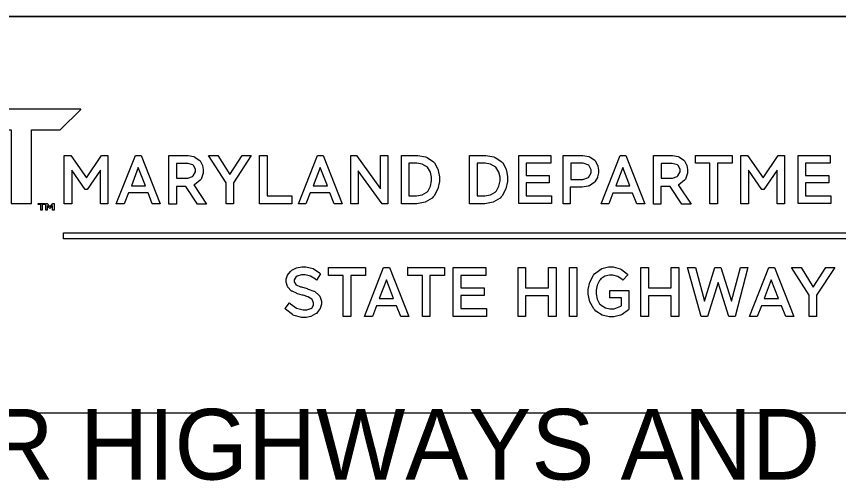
# Model space of a CAD drawing. Extents: x -113.6 to -105.1, y -201.8 to -190.8.
# Drawn here: x -108.497 to -107.419, y -200.619 to -200.01 of the extents above; entities that cross this region are included whole.
import ezdxf

# ---------------------------------------------------------------- set-up
doc = ezdxf.new("R2010")
doc.units = 0
for name, color, linetype in [('BORD-LINE', 7, 'Continuous'), ('MSHA-LOGO', 7, 'Continuous'), ('TTLB-TEXT', 7, 'Continuous'), ('USER-LINE', 7, 'Continuous')]:
    doc.layers.add(name, color=color, linetype=linetype)

msp = doc.modelspace()

# ---------------------------------------------------------------- linework, layer by layer
at = {"layer": 'BORD-LINE'}
msp.add_line((-105.4316, -200.01), (-109.9045, -200.01), dxfattribs=at)
at = {"layer": 'MSHA-LOGO'}
for points in [[(-108.5686, -200.1319), (-108.5686, -200.1591), (-108.5042, -200.1591), (-108.5042, -200.2556), (-108.4773, -200.2556), (-108.4773, -200.1591), (-108.4397, -200.1591), (-108.4127, -200.1321), (-108.4127, -200.1319)], [(-108.4345, -200.1924), (-108.4256, -200.1924), (-108.4053, -200.222), (-108.3857, -200.1924), (-108.3772, -200.1924), (-108.3772, -200.2559), (-108.387, -200.2559), (-108.387, -200.2118), (-108.4043, -200.2371), (-108.407, -200.2371), (-108.4246, -200.2118), (-108.4246, -200.2559), (-108.4345, -200.2559)], [(-108.3409, -200.1924), (-108.3333, -200.1924), (-108.3085, -200.2559), (-108.3189, -200.2559), (-108.3245, -200.2418), (-108.3503, -200.2418), (-108.3559, -200.2559), (-108.3661, -200.2559)], [(-108.297, -200.2562), (-108.297, -200.1927), (-108.2748, -200.1927), (-108.272, -200.1927), (-108.2644, -200.1941), (-108.2636, -200.1944), (-108.2629, -200.1946), (-108.2572, -200.1985), (-108.2568, -200.199), (-108.2563, -200.1995), (-108.2534, -200.2047), (-108.2532, -200.2053), (-108.253, -200.2058), (-108.2522, -200.2111), (-108.2522, -200.2128), (-108.2522, -200.2157), (-108.2549, -200.2235), (-108.2554, -200.2243), (-108.256, -200.2251), (-108.2636, -200.2309), (-108.2646, -200.2312), (-108.2476, -200.2566), (-108.2597, -200.2566), (-108.2751, -200.2332), (-108.2872, -200.2332), (-108.2872, -200.2566), (-108.297, -200.2566)], [(-108.2123, -200.2286), (-108.2123, -200.2562), (-108.2221, -200.2562), (-108.2221, -200.2286), (-108.245, -200.1924), (-108.2329, -200.1924), (-108.2172, -200.2177), (-108.2011, -200.1924), (-108.1893, -200.1924)], [(-108.1782, -200.1924), (-108.1684, -200.1924), (-108.1684, -200.2457), (-108.136, -200.2457), (-108.136, -200.2559), (-108.1782, -200.2559)], [(-108.1023, -200.1924), (-108.0948, -200.1924), (-108.0699, -200.2559), (-108.0804, -200.2559), (-108.0859, -200.2418), (-108.1118, -200.2418), (-108.1173, -200.2559), (-108.1272, -200.2559)], [(-108.0175, -200.2562), (-108.049, -200.2128), (-108.049, -200.2562), (-108.0584, -200.2562), (-108.0584, -200.1927), (-108.0509, -200.1927), (-108.0195, -200.2362), (-108.0195, -200.1927), (-108.01, -200.1927), (-108.01, -200.2562)], [(-107.992, -200.1924), (-107.9743, -200.1924), (-107.9706, -200.1924), (-107.9604, -200.1943), (-107.9593, -200.1947), (-107.9582, -200.1951), (-107.9498, -200.2009), (-107.9491, -200.2016), (-107.9486, -200.2024), (-107.9442, -200.2106), (-107.9439, -200.2115), (-107.9437, -200.2124), (-107.9423, -200.2206), (-107.9423, -200.2233), (-107.9423, -200.2266), (-107.9443, -200.2364), (-107.9491, -200.2454), (-107.9505, -200.247), (-107.9518, -200.2485), (-107.9608, -200.2537), (-107.9717, -200.2559), (-107.9753, -200.2559), (-107.992, -200.2559)], [(-107.9027, -200.1924), (-107.885, -200.1924), (-107.8813, -200.1924), (-107.871, -200.1943), (-107.87, -200.1947), (-107.8689, -200.1951), (-107.8605, -200.2009), (-107.8598, -200.2016), (-107.8592, -200.2024), (-107.8548, -200.2106), (-107.8546, -200.2115), (-107.8543, -200.2124), (-107.8529, -200.2206), (-107.8529, -200.2233), (-107.8529, -200.2266), (-107.8549, -200.2364), (-107.8597, -200.2454), (-107.8611, -200.247), (-107.8625, -200.2485), (-107.8715, -200.2537), (-107.8824, -200.2559), (-107.886, -200.2559), (-107.9027, -200.2559)], [(-107.8382, -200.1924), (-107.796, -200.1924), (-107.796, -200.2026), (-107.8284, -200.2026), (-107.8284, -200.2187), (-107.798, -200.2187), (-107.798, -200.2286), (-107.8284, -200.2286), (-107.8284, -200.2454), (-107.795, -200.2454), (-107.795, -200.2556), (-107.8382, -200.2556)], [(-107.78, -200.2562), (-107.78, -200.1927), (-107.757, -200.1927), (-107.7541, -200.1927), (-107.7461, -200.1941), (-107.7453, -200.1944), (-107.7445, -200.1947), (-107.7385, -200.1988), (-107.7381, -200.1993), (-107.7377, -200.1998), (-107.7346, -200.2053), (-107.7345, -200.2059), (-107.7343, -200.2065), (-107.7335, -200.2117), (-107.7335, -200.2135), (-107.7335, -200.2154), (-107.7346, -200.2205), (-107.7348, -200.221), (-107.735, -200.2216), (-107.7383, -200.2271), (-107.7387, -200.2276), (-107.7391, -200.2281), (-107.7454, -200.2322), (-107.7462, -200.2325), (-107.7471, -200.2329), (-107.7548, -200.2342), (-107.7574, -200.2342), (-107.7705, -200.2342), (-107.7705, -200.2559), (-107.78, -200.2559)], [(-107.705, -200.1924), (-107.6975, -200.1924), (-107.6726, -200.2559), (-107.6831, -200.2559), (-107.6887, -200.2421), (-107.7145, -200.2421), (-107.7201, -200.2562), (-107.7302, -200.2562)], [(-107.6615, -200.2562), (-107.6615, -200.1927), (-107.6392, -200.1927), (-107.6365, -200.1927), (-107.6289, -200.1941), (-107.6281, -200.1944), (-107.6274, -200.1946), (-107.6217, -200.1985), (-107.6212, -200.199), (-107.6208, -200.1995), (-107.6179, -200.2047), (-107.6176, -200.2053), (-107.6175, -200.2058), (-107.6167, -200.2111), (-107.6167, -200.2128), (-107.6167, -200.2157), (-107.6194, -200.2235), (-107.6199, -200.2243), (-107.6205, -200.2251), (-107.6281, -200.2309), (-107.6291, -200.2312), (-107.6121, -200.2566), (-107.6242, -200.2566), (-107.6396, -200.2332), (-107.6517, -200.2332), (-107.6517, -200.2566), (-107.6615, -200.2566)], [(-107.6062, -200.1924), (-107.5581, -200.1924), (-107.5581, -200.2026), (-107.5774, -200.2026), (-107.5774, -200.2559), (-107.5872, -200.2559), (-107.5872, -200.2026), (-107.6062, -200.2026)], [(-107.5466, -200.1924), (-107.5378, -200.1924), (-107.5175, -200.222), (-107.4979, -200.1924), (-107.4893, -200.1924), (-107.4893, -200.2559), (-107.4992, -200.2559), (-107.4992, -200.2118), (-107.5165, -200.2371), (-107.5191, -200.2371), (-107.5368, -200.2118), (-107.5368, -200.2559), (-107.5466, -200.2559)], [(-107.4717, -200.1924), (-107.4295, -200.1924), (-107.4295, -200.2026), (-107.4619, -200.2026), (-107.4619, -200.2187), (-107.4314, -200.2187), (-107.4314, -200.2286), (-107.4619, -200.2286), (-107.4619, -200.2454), (-107.4285, -200.2454), (-107.4285, -200.2556), (-107.4717, -200.2556)], [(-108.3464, -200.2325), (-108.3278, -200.2325), (-108.3373, -200.2085)], [(-108.2872, -200.2029), (-108.2872, -200.2223), (-108.2744, -200.2223), (-108.2722, -200.2223), (-108.2662, -200.2201), (-108.2656, -200.2197), (-108.2651, -200.2193), (-108.2623, -200.2139), (-108.2623, -200.2122), (-108.2623, -200.2104), (-108.2648, -200.2057), (-108.2653, -200.2053), (-108.2658, -200.2048), (-108.2725, -200.2029), (-108.2748, -200.2029)], [(-108.1079, -200.2325), (-108.0892, -200.2325), (-108.0987, -200.2085)], [(-107.9822, -200.2029), (-107.9822, -200.2457), (-107.9747, -200.2457), (-107.9722, -200.2457), (-107.9649, -200.2442), (-107.9589, -200.2408), (-107.958, -200.2398), (-107.9571, -200.2388), (-107.9538, -200.2327), (-107.9524, -200.2257), (-107.9524, -200.2233), (-107.9524, -200.2211), (-107.9538, -200.2143), (-107.9579, -200.2078), (-107.9647, -200.2039), (-107.9719, -200.2026), (-107.9743, -200.2026), (-107.9822, -200.2026)], [(-107.8925, -200.2029), (-107.8925, -200.2457), (-107.885, -200.2457), (-107.8825, -200.2457), (-107.8752, -200.2442), (-107.8692, -200.2408), (-107.8683, -200.2398), (-107.8674, -200.2388), (-107.8642, -200.2327), (-107.8627, -200.2257), (-107.8627, -200.2233), (-107.8627, -200.2211), (-107.8641, -200.2143), (-107.8682, -200.2078), (-107.875, -200.2039), (-107.8823, -200.2026), (-107.8847, -200.2026), (-107.8925, -200.2026)], [(-107.7698, -200.2026), (-107.7698, -200.224), (-107.7567, -200.224), (-107.7542, -200.224), (-107.7464, -200.2213), (-107.743, -200.2152), (-107.743, -200.2131), (-107.743, -200.2112), (-107.7462, -200.2053), (-107.7536, -200.2026), (-107.7561, -200.2026)], [(-107.7109, -200.2325), (-107.6922, -200.2325), (-107.7017, -200.2085)], [(-107.6513, -200.2029), (-107.6513, -200.2223), (-107.6386, -200.2223), (-107.6364, -200.2223), (-107.6303, -200.2201), (-107.6297, -200.2197), (-107.6293, -200.2193), (-107.6265, -200.2139), (-107.6265, -200.2122), (-107.6265, -200.2104), (-107.6289, -200.2057), (-107.6294, -200.2053), (-107.6299, -200.2048), (-107.6367, -200.2029), (-107.6389, -200.2029)], [(-108.4687, -200.2556), (-108.4598, -200.2556), (-108.4598, -200.2571), (-108.4632, -200.2571), (-108.4632, -200.2645), (-108.465, -200.2645), (-108.465, -200.2571), (-108.4687, -200.2571)], [(-108.4585, -200.2556), (-108.4569, -200.2556), (-108.4531, -200.2599), (-108.4494, -200.2556), (-108.4478, -200.2556), (-108.4478, -200.2645), (-108.4499, -200.2645), (-108.4499, -200.2581), (-108.4533, -200.2622), (-108.4567, -200.2581), (-108.4567, -200.2645), (-108.4585, -200.2645)], [(-108.4354, -200.2942), (-106.3187, -200.2942), (-106.3187, -200.3021), (-108.4354, -200.3021)], [(-108.1093, -200.3815), (-108.1096, -200.3811), (-108.1139, -200.3785), (-108.1144, -200.3782), (-108.115, -200.3781), (-108.1208, -200.3761), (-108.1214, -200.376), (-108.1221, -200.3758), (-108.1285, -200.374), (-108.1291, -200.3737), (-108.1297, -200.3735), (-108.1356, -200.3709), (-108.1361, -200.3705), (-108.1367, -200.3702), (-108.1409, -200.3656), (-108.1412, -200.3651), (-108.1416, -200.3645), (-108.1432, -200.3587), (-108.1432, -200.3567), (-108.1432, -200.355), (-108.1415, -200.3497), (-108.1378, -200.3447), (-108.1368, -200.3439), (-108.1357, -200.343), (-108.1296, -200.34), (-108.1228, -200.3387), (-108.1205, -200.3387), (-108.1173, -200.3387), (-108.1077, -200.3411), (-108.0995, -200.3465), (-108.0981, -200.3481), (-108.1035, -200.3561), (-108.1047, -200.3549), (-108.1115, -200.351), (-108.1185, -200.3493), (-108.1208, -200.3493), (-108.123, -200.3493), (-108.1289, -200.3509), (-108.1294, -200.3513), (-108.13, -200.3516), (-108.1329, -200.3557), (-108.1329, -200.357), (-108.1329, -200.3583), (-108.1308, -200.3618), (-108.1304, -200.3622), (-108.13, -200.3625), (-108.1244, -200.3649), (-108.1237, -200.3651), (-108.123, -200.3652), (-108.1158, -200.3674), (-108.1151, -200.3676), (-108.1143, -200.3679), (-108.1071, -200.3706), (-108.1064, -200.3709), (-108.1058, -200.3712), (-108.1002, -200.376), (-108.0997, -200.3766), (-108.0993, -200.3773), (-108.0971, -200.3838), (-108.0971, -200.3859), (-108.0971, -200.3878), (-108.0988, -200.3936), (-108.1025, -200.3989), (-108.1035, -200.3998), (-108.1046, -200.4006), (-108.1107, -200.4038), (-108.1171, -200.4052), (-108.1192, -200.4052), (-108.1229, -200.4052), (-108.1327, -200.4025), (-108.1339, -200.402), (-108.1351, -200.4014), (-108.1441, -200.3945), (-108.1448, -200.3936), (-108.1387, -200.3859), (-108.1374, -200.3875), (-108.1298, -200.3929), (-108.1211, -200.3953), (-108.1182, -200.3953), (-108.1162, -200.3953), (-108.1107, -200.3936), (-108.1103, -200.3933), (-108.1098, -200.393), (-108.1074, -200.3889), (-108.1074, -200.3875), (-108.1074, -200.386), (-108.109, -200.3818)], [(-108.0879, -200.3397), (-108.0393, -200.3397), (-108.0393, -200.3503), (-108.0585, -200.3503), (-108.0585, -200.4039), (-108.0684, -200.4039), (-108.0684, -200.35), (-108.0876, -200.35), (-108.0876, -200.3397)], [(-108.0154, -200.3397), (-108.0077, -200.3397), (-107.9825, -200.4039), (-107.993, -200.4039), (-107.9984, -200.3898), (-108.0246, -200.3898), (-108.03, -200.4039), (-108.0403, -200.4039)], [(-107.9841, -200.3397), (-107.9355, -200.3397), (-107.9355, -200.3503), (-107.9546, -200.3503), (-107.9546, -200.4039), (-107.9645, -200.4039), (-107.9645, -200.35), (-107.9837, -200.35), (-107.9837, -200.3397)], [(-107.924, -200.3397), (-107.8812, -200.3397), (-107.8812, -200.3503), (-107.9141, -200.3503), (-107.9141, -200.3664), (-107.8834, -200.3664), (-107.8834, -200.3763), (-107.9141, -200.3763), (-107.9141, -200.3933), (-107.8805, -200.3933), (-107.8805, -200.4039), (-107.924, -200.4039)], [(-107.7991, -200.3766), (-107.8291, -200.3766), (-107.8291, -200.4039), (-107.839, -200.4039), (-107.839, -200.3397), (-107.8291, -200.3397), (-107.8291, -200.3664), (-107.7991, -200.3664), (-107.7991, -200.3397), (-107.7892, -200.3397), (-107.7892, -200.4039), (-107.7991, -200.4039)], [(-107.7716, -200.3397), (-107.7617, -200.3397), (-107.7617, -200.4039), (-107.7716, -200.4039)], [(-107.7185, -200.3696), (-107.6936, -200.3696), (-107.6936, -200.3943), (-107.6943, -200.3951), (-107.7026, -200.4013), (-107.7035, -200.4017), (-107.7046, -200.4021), (-107.7134, -200.4043), (-107.7163, -200.4043), (-107.7194, -200.4043), (-107.7285, -200.402), (-107.7369, -200.3968), (-107.7383, -200.3953), (-107.7398, -200.3937), (-107.7448, -200.3848), (-107.747, -200.3748), (-107.747, -200.3715), (-107.747, -200.3683), (-107.7449, -200.3587), (-107.74, -200.3497), (-107.7387, -200.3481), (-107.7372, -200.3465), (-107.7291, -200.341), (-107.7205, -200.3387), (-107.7176, -200.3387), (-107.7142, -200.3387), (-107.7052, -200.3412), (-107.7041, -200.3416), (-107.7032, -200.3421), (-107.6955, -200.3485), (-107.6949, -200.3493), (-107.7016, -200.3564), (-107.7025, -200.3553), (-107.7081, -200.3513), (-107.7147, -200.3497), (-107.7169, -200.3497), (-107.719, -200.3497), (-107.7251, -200.3511), (-107.7304, -200.3547), (-107.7313, -200.3558), (-107.7322, -200.3567), (-107.7354, -200.3627), (-107.7367, -200.3695), (-107.7367, -200.3718), (-107.7367, -200.3741), (-107.7353, -200.3811), (-107.732, -200.3871), (-107.731, -200.3882), (-107.73, -200.3892), (-107.7245, -200.3925), (-107.7184, -200.394), (-107.7163, -200.394), (-107.713, -200.394), (-107.7041, -200.3902), (-107.7032, -200.3895), (-107.7032, -200.3795), (-107.7185, -200.3795)], [(-107.638, -200.3766), (-107.6681, -200.3766), (-107.6681, -200.4039), (-107.678, -200.4039), (-107.678, -200.3397), (-107.6681, -200.3397), (-107.6681, -200.3664), (-107.638, -200.3664), (-107.638, -200.3397), (-107.6281, -200.3397), (-107.6281, -200.4039), (-107.638, -200.4039)], [(-107.5543, -200.4039), (-107.5626, -200.4039), (-107.5767, -200.3593), (-107.5904, -200.4039), (-107.5987, -200.4039), (-107.6166, -200.3397), (-107.6064, -200.3397), (-107.5943, -200.384), (-107.5808, -200.3397), (-107.5728, -200.3397), (-107.5591, -200.384), (-107.5473, -200.3397), (-107.5374, -200.3397)], [(-107.5102, -200.3397), (-107.5025, -200.3397), (-107.4773, -200.4039), (-107.4878, -200.4039), (-107.4936, -200.3898), (-107.5198, -200.3898), (-107.5252, -200.4039), (-107.5355, -200.4039)], [(-107.4473, -200.376), (-107.4473, -200.4039), (-107.4572, -200.4039), (-107.4572, -200.376), (-107.4802, -200.3397), (-107.4677, -200.3397), (-107.4517, -200.3654), (-107.4354, -200.3397), (-107.4236, -200.3397)], [(-108.0211, -200.3802), (-108.0023, -200.3802), (-108.0118, -200.3558)], [(-107.5163, -200.3802), (-107.4974, -200.3802), (-107.507, -200.3558)]]:
    msp.add_lwpolyline(points, close=True, dxfattribs=at)
at = {"layer": 'USER-LINE'}
msp.add_lwpolyline([(-106.1825, -200.5307), (-109.1536, -200.5307), (-109.1536, -200.01), (-106.1825, -200.01)], close=True, dxfattribs=at)

# ---------------------------------------------------------------- texts
at = {"layer": 'TTLB-TEXT'}
msp.add_text('STANDARDS FOR HIGHWAYS AND INCIDENTAL STRUCTURES', height=0.09269, dxfattribs=at).set_placement((-109.5087, -200.618))

doc.saveas('drawing.dxf')
